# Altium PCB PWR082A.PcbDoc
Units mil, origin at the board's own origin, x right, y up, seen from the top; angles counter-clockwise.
Board outline 3000 x 2000 mil, 4 copper layers (Top, Inner Layer 2, Inner Layer 3, Bottom), stack 35.4 mil thick; 57 components, 21 nets, 108 pads, 176 vias.
Unrouted connection lines stored in the file: 167.
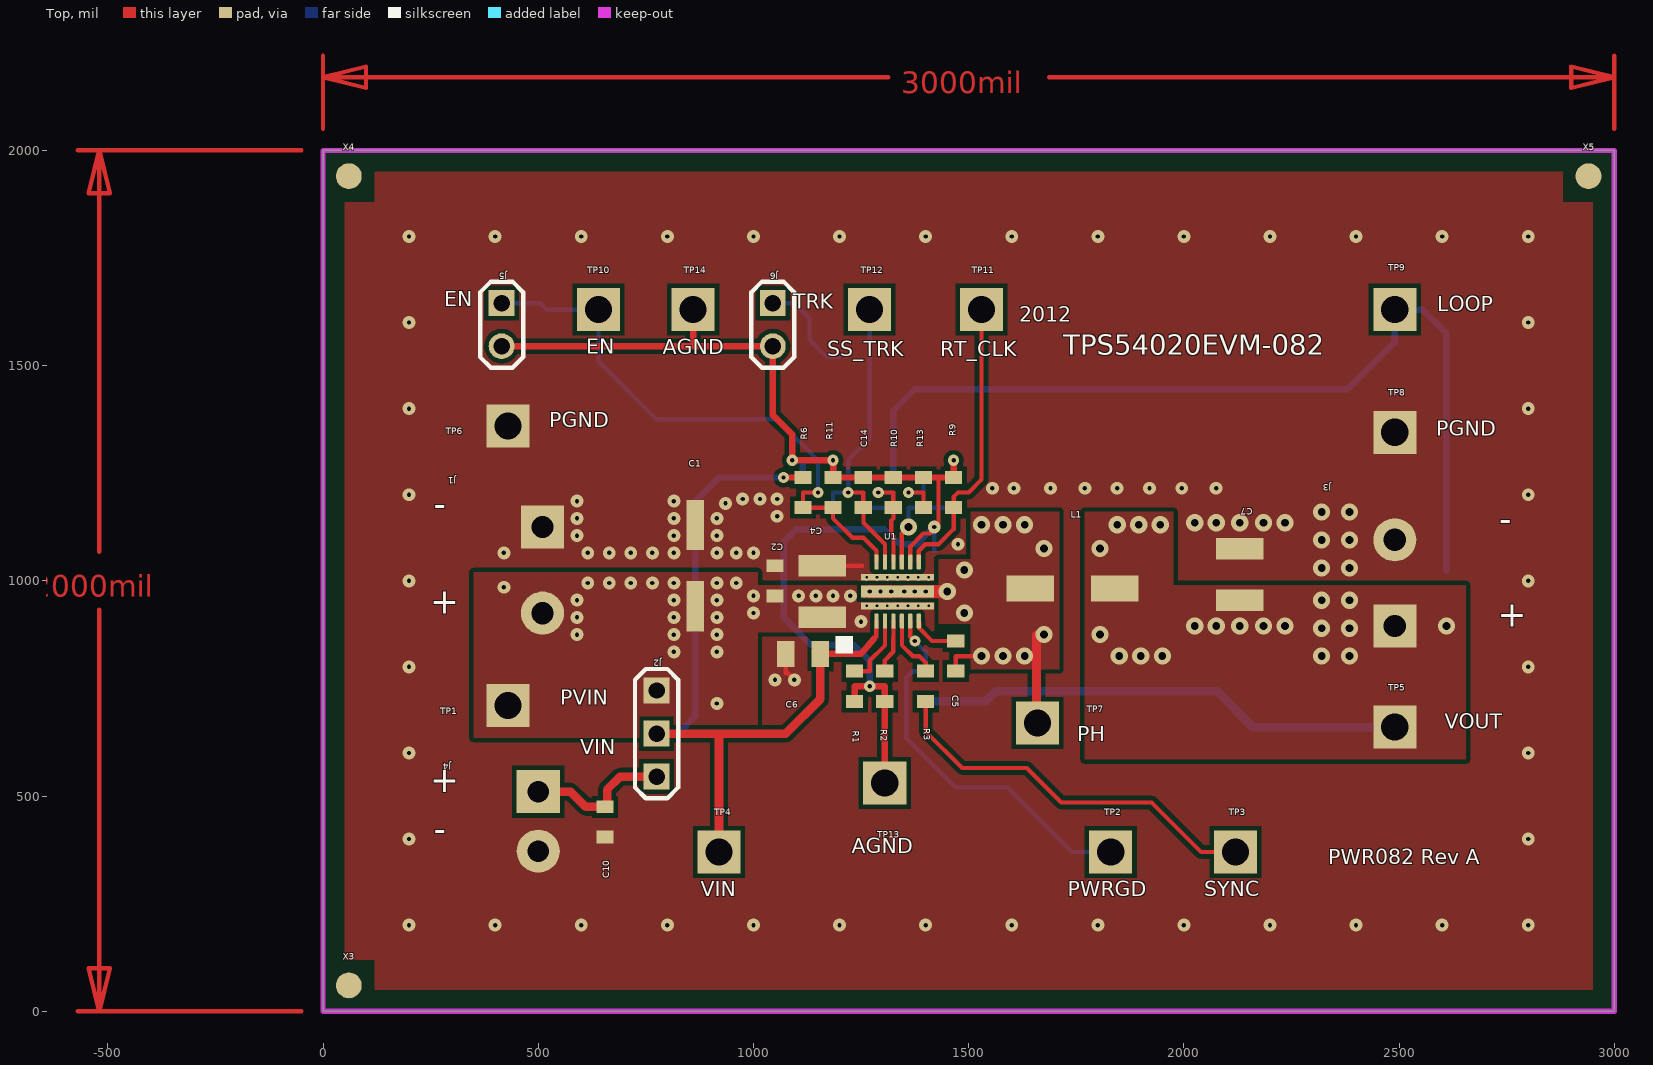
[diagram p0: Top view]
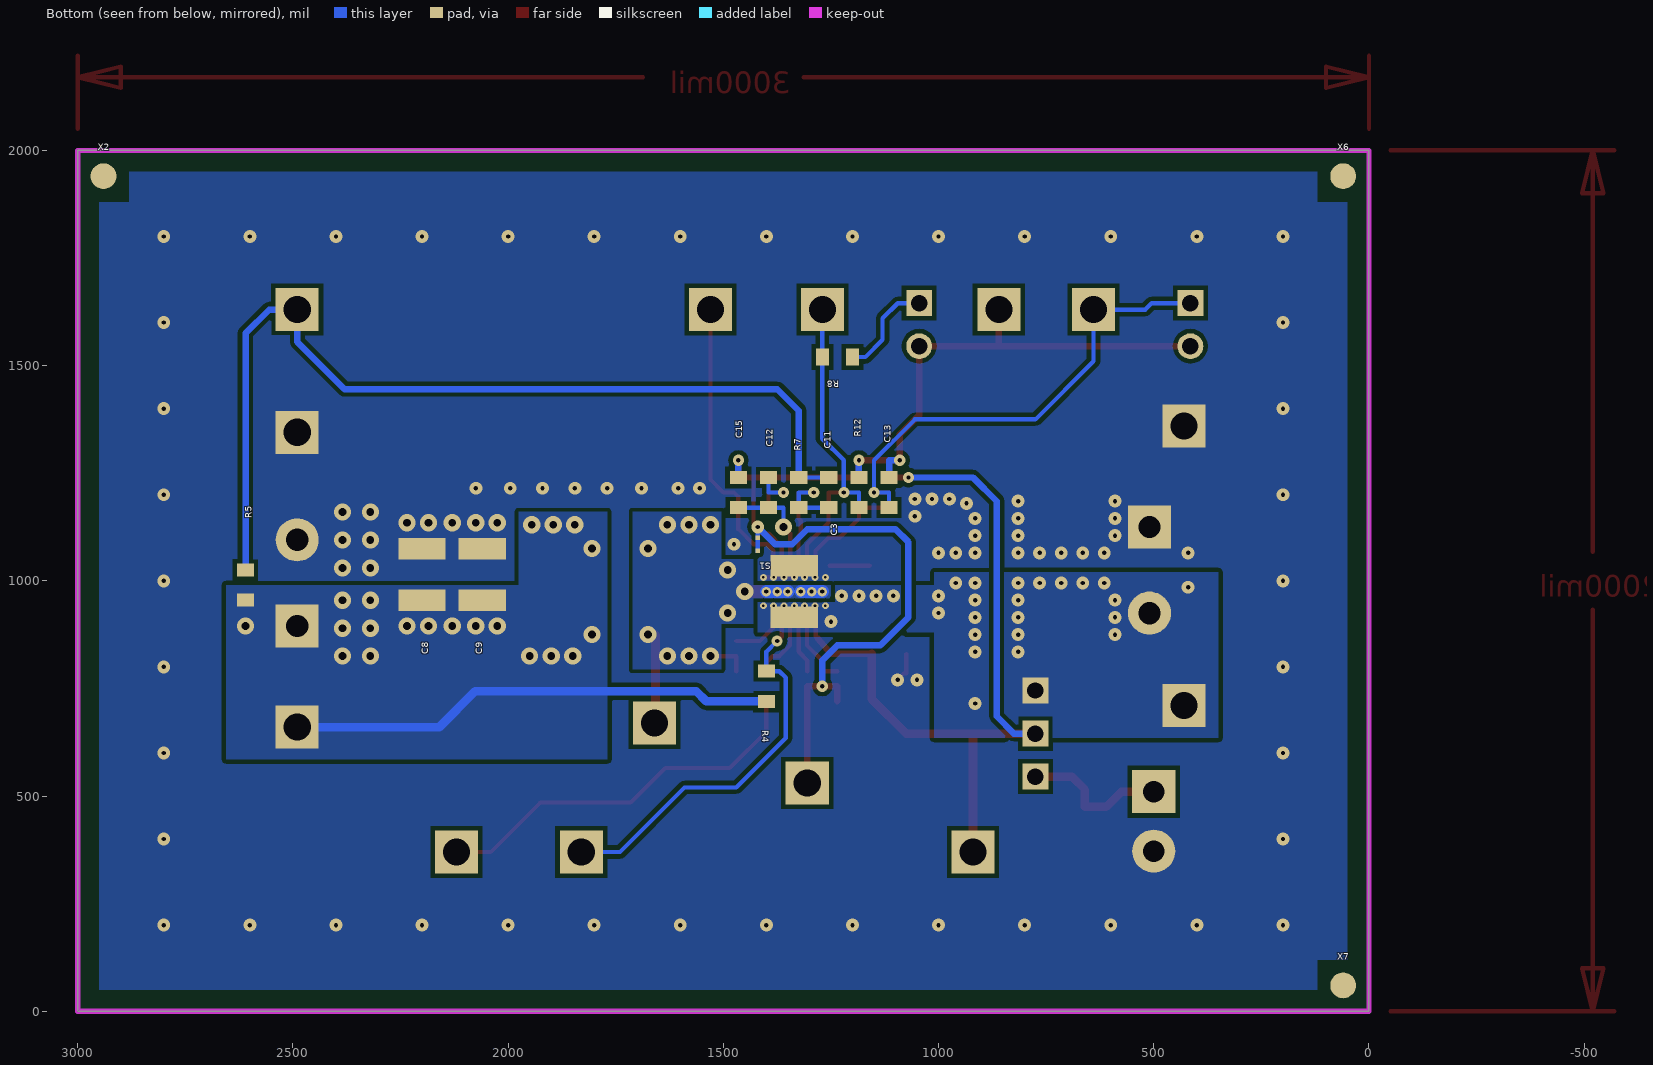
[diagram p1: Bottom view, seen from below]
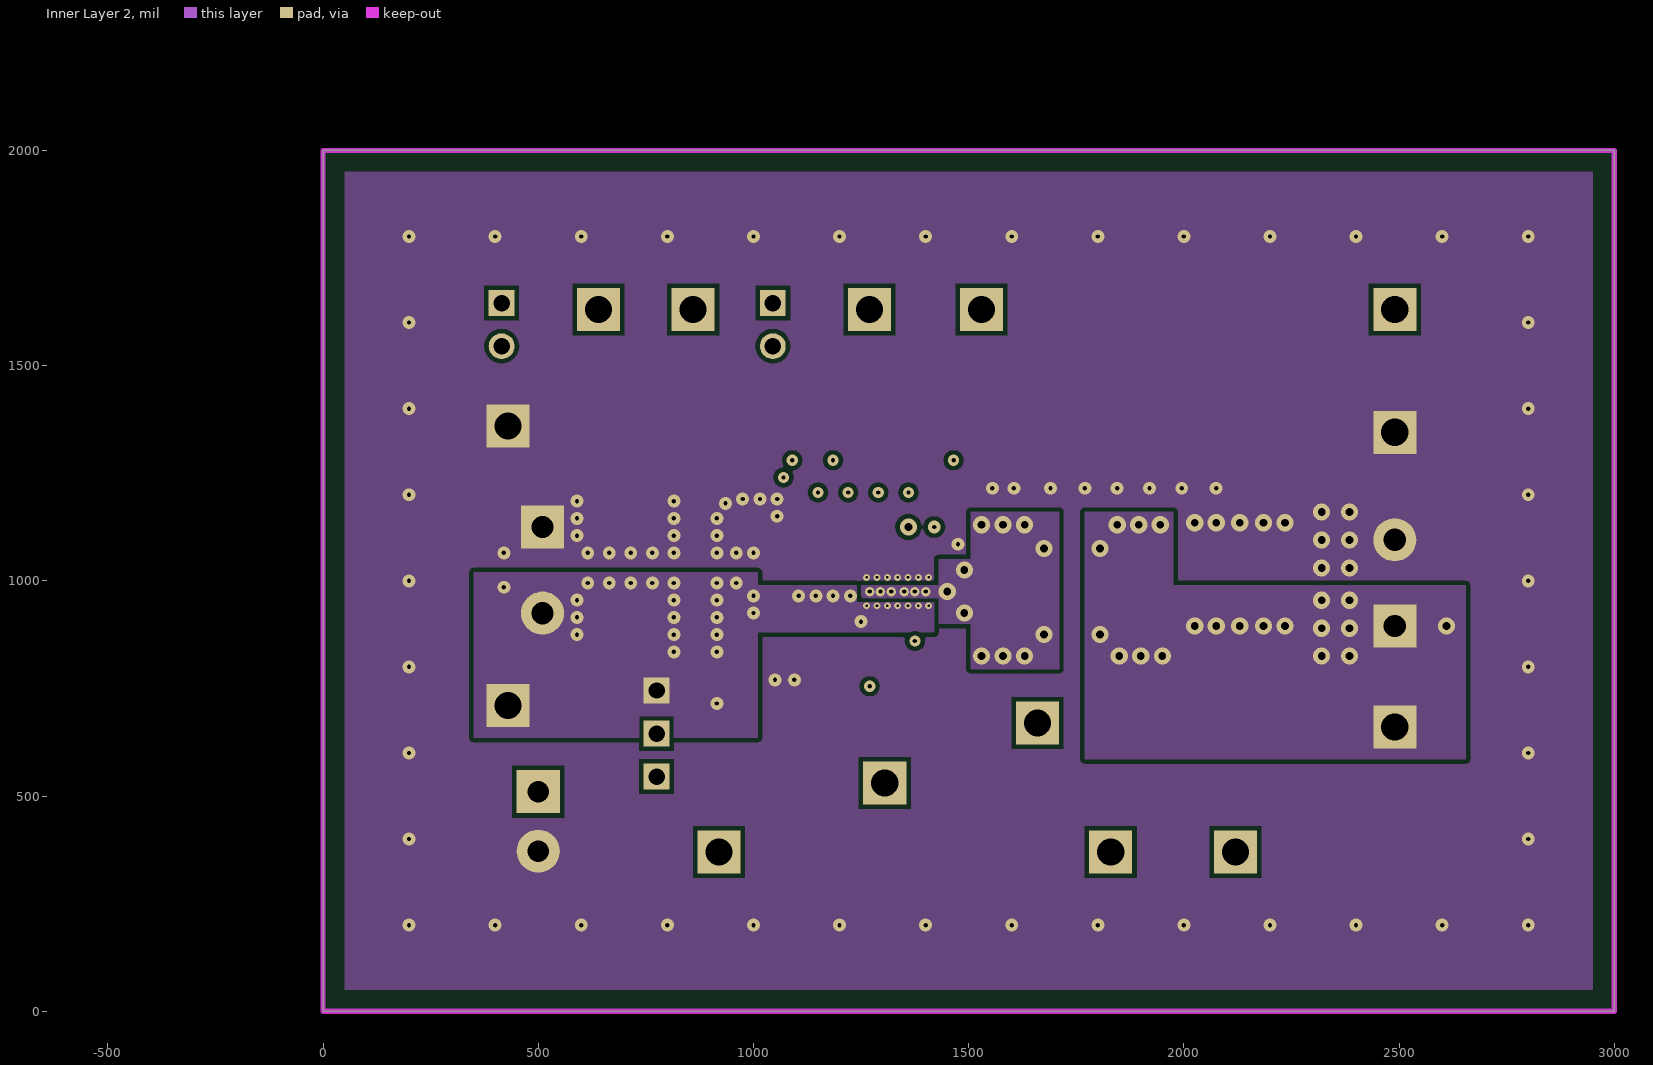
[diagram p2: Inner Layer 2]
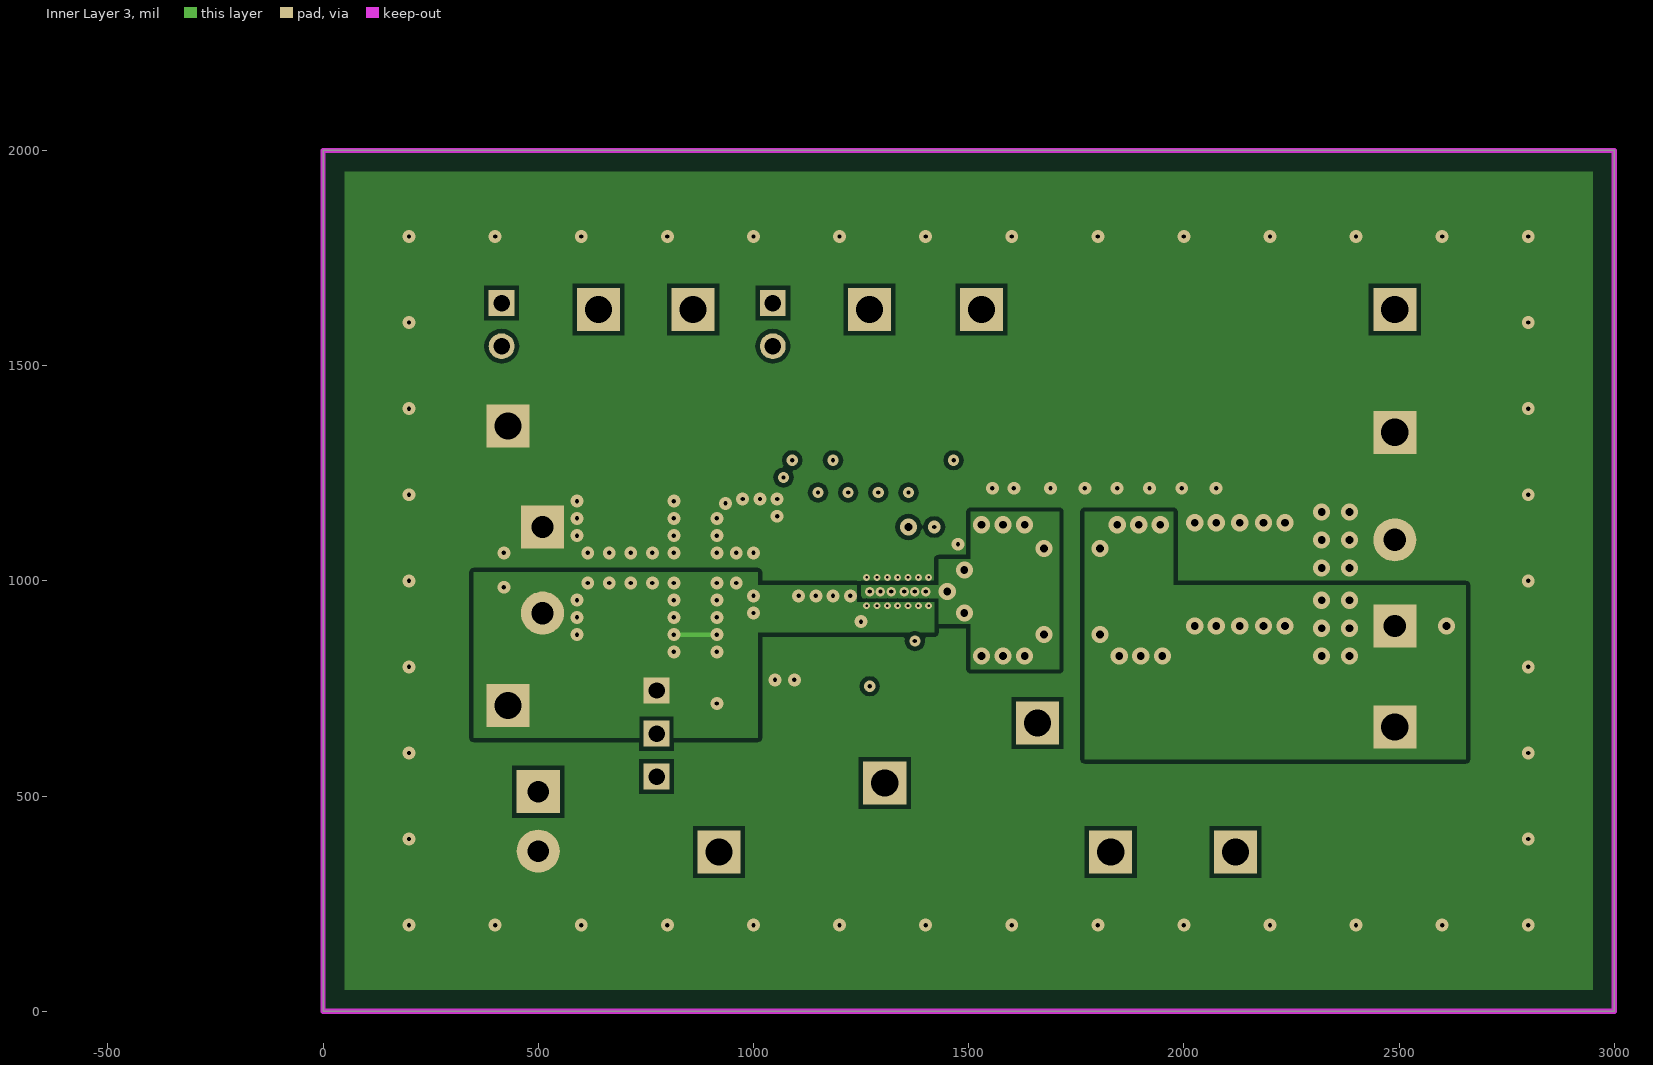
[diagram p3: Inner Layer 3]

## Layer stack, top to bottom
Solder Mask Top: solder mask 0.4, Solder Resist, Dk 3.5
Top: signal copper 1.35
Dielectric 1: dielectric 10, FR-4, Dk 4.3
Inner Layer 2: signal copper 1.35
Dielectric2: dielectric 10, FR-4, Dk 4.3
Inner Layer 3: signal copper 1.35
Dielectric3: dielectric 10, FR-4, Dk 4.3
Bottom: signal copper 1.35
Solder Mask Bottom: solder mask 0.4, Solder Resist, Dk 3.5

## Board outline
0,0 3000,0 3000,2000 0,2000

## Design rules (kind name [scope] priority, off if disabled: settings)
Clearance "Clearance - Default - DEFAULT- SMD" [IsVia vs IsSMTPin] p1: gap=10 ignorepadtopadclearanceinfootprint=FALSE
Clearance "Clearance - Default - DEFAULT - Via" [IsVia vs IsVia] p2: gap=10 ignorepadtopadclearanceinfootprint=FALSE
Clearance "Clearance - Default - DEFAULT - Net" [All] p3: gap=10 ignorepadtopadclearanceinfootprint=FALSE except(0: Arc-Hole Track-Hole SMDPad-Hole THPad-Hole Via-Hole Fill-Hole Poly-Hole Region-Hole Text-Hole; 1: Arc-Text Track-Text SMDPad-Text THPad-Text Via-Text Fill-Text Poly-Text Region-Text; 8: Arc-Arc Arc-Track Arc-SMDPad Arc-THPad Track-Track Track-SMDPad Track-THPad SMDPad-SMDPad SMDPad-THPad SMDPad-Via THPad-THPad)
ComponentClearance "ComponentClearance - Default - DEFAULT" [All] p1: gap=6 collisioncheckmode=3 verticalgap=10 showdistances=FALSE
HoleToHoleClearance "HoleToHoleClearance - Default - DEFAULT" [All] p1: gap=6 allowstackedmicrovias=TRUE
Length "Default Length" [All] p1: maxlimit=50000 minlimit=0
MaxMinImpedance "Default Impedance" [All] p1: minimum=50.00 maximum=150.0
ParallelSegment "Default Parallel Segment Same Layer" [All] p1: limit=1000 gap=200
ParallelSegment "Default Parallel Segment Adjasent" [All] p2: limit=1000 gap=200
PlaneConnect "Default PlaneConnect" [All] p1: planeconnectstyle=Direct reliefexpansion=20 reliefentries=4 reliefconductorwidth=10 reliefairgap=10
PolygonConnect "PolygonConnect - Default SMT" [IsSMTPin] p1: connectstyle=Direct reliefconductorwidth=10 reliefentries=4 polygonreliefangle="45 Angle" airgapwidth=10
PolygonConnect "PolygonConnect - Default Pad" [All] p2: connectstyle=Direct reliefconductorwidth=10 reliefentries=4 polygonreliefangle="45 Angle" airgapwidth=10
RoutingLayers "RoutingLayers - Default - DEFAULT" [All] p1: top layer_v5=TRUE mid layer 1_v5=TRUE mid layer 2_v5=TRUE bottom layer_v5=TRUE
RoutingPriority "RoutingPriority - Default - DEFAULT" [All] p1: routingpriority=3
RoutingTopology "Default Routing Topology" [All] p1: topology=Shortest
RoutingVias "RoutingVias - Default - DEFAULT" [All] p1: holewidth=37 width=55 viastyle="Through Hole" minholewidth=37 minwidth=55 maxholewidth=37 maxwidth=55
SMDToCorner "SMDToCorner - Default - DEFAULT" [All] p1: distance=100000
SolderMaskExpansion "SolderMaskExpansion from CAM settings" [All] p1: expansion=1
Width "Default Width" [All] p1: maxlimit=25 minlimit=6 preferedwidth=10
22 further rules are at their usual default settings.

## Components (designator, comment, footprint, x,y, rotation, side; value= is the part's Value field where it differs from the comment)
C1 "CAP_ALUM_FK-D" CAP_ALUM_FK-D 865,1035 r180 top
C2 "C603" C603 1050,1000 r270 top
C3 "C1210" C1210 1335,975 r90 bottom
C4 "C1210" C1210 1160,975 r90 top
C5 "C603" C603 1470,825 r90 top
C6 "C0805" C0805 1115,830 r0 top
C7 "C1210" C1210 2130,1015 r90 top
C8 "C1210" C1210 2200,1015 r90 bottom
C9 "C1210" C1210 2060,1015 r90 bottom
C10 "C603" C603 655,440 r90 top
C11 "C603" C603 1255,1205 r90 bottom
C12 "C603" C603 1395,1205 r270 bottom
C13 "C603" C603 1115,1205 r270 bottom
C14 "C603" C603 1255,1205 r270 top
C15 "C603" C603 1465,1205 r270 bottom
J1 "TB_2X5.1MM" TB_2X5.1MM 510,1125 r270 top
J2 "HDR100_1X3" HDR100_1X3 775,745 r270 top
J3 "TB_2X5.1MM" TB_2X5.1MM 2490,895 r90 top
J4 "TB_2X3.5MM" TB_2X3.5MM 500,510 r270 top
J5 "HDR100_1X2" HDR100_1X2 415,1645 r270 top
J6 "HDR100_1X2" HDR100_1X2 1045,1645 r270 top
L1 "IND_272_X_276" IND_272_X_276 1741,982 r0 top
R1 "R603" R603 1235,755 r270 top
R2 "R603" R603 1305,755 r270 top
R3 "R603" R603 1400,755 r90 top
R4 "R603" R603 1400,755 r90 bottom
R5 "R603" R603 2610,990 r90 bottom
R6 "R603" R603 1115,1205 r270 top
R7 "R603" R603 1325,1205 r270 bottom
R8 "R603" R603 1235,1520 r0 bottom
R9 "R603" R603 1465,1205 r90 top
R10 "R603" R603 1325,1205 r90 top
R11 "R603" R603 1185,1205 r90 top
R12 "R603" R603 1185,1205 r90 bottom
R13 "R603" R603 1395,1205 r90 top
S1 "WIRE" WIRE 1420,1070 r0 bottom
TP1 "TH-63" TH-63 430,710 r0 top
TP2 "TH-63" TH-63 1830,370 r0 top
TP3 "TH-63" TH-63 2120,370 r0 top
TP4 "TH-63" TH-63 920,370 r0 top
TP5 "TH-63" TH-63 2490,660 r0 top
TP6 "TH-63" TH-63 430,1360 r0 top
TP7 "TH-63" TH-63 1660,670 r0 top
TP8 "TH-63" TH-63 2490,1345 r0 top
TP9 "TH-63" TH-63 2490,1630 r0 top
TP10 "TH-63" TH-63 640,1630 r0 top
TP11 "TH-63" TH-63 1530,1630 r0 top
TP12 "TH-63" TH-63 1270,1630 r0 top
TP13 "TH-63" TH-63 1305,530 r0 top
TP14 "TH-63" TH-63 860,1630 r0 top
U1 "QFN15[RUW]" QFN15[RUW] 1335,975 r0 top
X2 "TOP_FIDO_60-MIL" TOP_FIDO_60-MIL 2940,1940 r180 bottom
X3 "TOP_FIDO_60-MIL" TOP_FIDO_60-MIL 60,60 r0 top
X4 "TOP_FIDO_60-MIL" TOP_FIDO_60-MIL 60,1940 r0 top
X5 "TOP_FIDO_60-MIL" TOP_FIDO_60-MIL 2940,1940 r0 top
X6 "TOP_FIDO_60-MIL" TOP_FIDO_60-MIL 60,1940 r180 bottom
X7 "TOP_FIDO_60-MIL" TOP_FIDO_60-MIL 60,60 r180 bottom

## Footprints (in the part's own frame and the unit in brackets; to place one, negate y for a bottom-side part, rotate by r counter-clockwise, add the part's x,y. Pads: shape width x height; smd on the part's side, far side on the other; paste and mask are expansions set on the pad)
C603 [mil]
  rect 30x40 smd mask+2: 1(-35,0) 2(35,0)
C0805 [mil]
  rect 40x60 smd mask+2: 1(-40,0) 2(40,0)
C1210 [mil]
  rect 50x110 smd mask+2: 1(60,0) 2(-60,0)
CAP_ALUM_FK-D [mil]
  rect 40x117 smd: 1(0,94.5) 2(0,-94.5)
HDR100_1X2 [mil]
  rect 60x60 hole 38: 1(0,0)
  round 60 hole 38: 2(100,0)
  silkscreen extent -50,-50 150,50
HDR100_1X3 [mil]
  rect 60x60 hole 38: 1(0,0) 2(100,0) 3(200,0)
  silkscreen extent -50,-50 250,50
IND_272_X_276 [mil]
  rect 110x60 smd: 1(-98,0) 2(98,0)
QFN15[RUW] [mil]
  rrect50% 10x35 smd mask+2: 1(-49.25,-68.47) 2(-29.55,-68.47) 3(-9.85,-68.47) 4(9.85,-68.47) 5(29.55,-68.47) 6(49.25,-68.47) 10(49.25,68.47) 11(29.55,68.47) 12(9.85,68.47) 13(-9.85,68.47) 14(-29.55,68.47) 15(-49.25,68.47)
  rect 169.29x15.75 smd mask+0.98: 7(0,-33.46) 9(0,33.46)
  rect 169.29x27.56 smd mask+0.98: 8(0,0)
  silkscreen extent -144,-144 -104,-104
R603 [mil]
  rect 30x40 smd: 1(-35,0) 2(35,0)
TB_2X3.5MM [mil]
  rect 100x100 hole 50: 1(0,0)
  round 100 hole 50: 2(138,0)
TB_2X5.1MM [mil]
  rect 100x100 hole 52: 1(0,0)
  round 100 hole 52: 2(200,0)
TH-63 [mil]
  rect 100x100 hole 63: 1(0,0)
TOP_FIDO_60-MIL [mil]
  round 60 smd: 1(0,0)
  Top pour cut-out: -60,60 60,60 60,-60 -60,-60 -60,60
WIRE [mil]
  rect 10x10 smd: 1(0,0) 2(0,-30)

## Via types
v1: diameter 30, hole 10, Top to Bottom, 103 vias
v2: diameter 40, hole 18, Top to Bottom, 43 vias
v3: diameter 16, hole 6, Top to Bottom, 14 vias
v4: diameter 26, hole 10, Top to Bottom, 10 vias
v5: diameter 22, hole 10, Top to Bottom, 6 vias

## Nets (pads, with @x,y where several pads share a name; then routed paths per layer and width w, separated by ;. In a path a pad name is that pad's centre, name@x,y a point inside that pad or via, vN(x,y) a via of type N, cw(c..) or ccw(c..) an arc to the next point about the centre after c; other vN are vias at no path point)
$$$3415: C12.1 R13.1 | length 140
  Top w10: v4(1360,1205) 1395,1205 R13.1
  Bottom w10: v4(1360,1205) 1395,1205 C12.1
$$$5685: J6.1 R8.1 | length 236.1
  Bottom w10: J6.1 1095,1645 1130,1610 1130,1560 1170,1520 R8.1
AGND: C13.1 C14.1 C15.1 J5.2 J6.2 R1.2 R2.2 R9.2 R10.2 R11.2 R12.2 R13.2 S1.2 TP13.1 TP14.1 U1.11 | length 3057.2
  Top w10: U1.11 1364.55,1080 1394.55,1110 1410,1110 v1(1420,1125) 1430,1130 1430,1240
  Top w15: J5.2 860,1545 ; TP14.1 860,1545 ; R1.2 1235,755 v4(1270,755) 1305,755 R2.2 TP13.1 ; v4(1465,1280) R9.2 1430,1240 R13.2 R10.2 C14.1 R11.2 v4(1185,1280) v4(1090,1280) 1090,1340 1045,1385 J6.2 860,1545
  Bottom w10: S1.2 v1(1420,1125)
  Bottom w15: v4(1090,1280) 1115,1280 C13.1 ; R12.2 v4(1185,1280) ; v4(1270,755) 1270,815 1235,850 1135,850 1070,915 1070,1090 1100,1120 1305,1120 1340,1085 1380,1085 v1(1420,1125) ; C15.1 v4(1465,1280)
BOOT: C5.2 U1.6 | length 114
  Top w10: U1.6 1385,902.58 1385,890 1415,860 C5.2
COMP: C12.2 C15.2 U1.12 | length 237.9
  Top w10: U1.12 1344.85,1110 v2(1360,1125)
  Bottom w10: v2(1360,1125) 1360,1170 C12.2 C15.2
EN: C13.2 J5.1 R6.2 R11.1 TP10.1 U1.15 | length 1424.8
  Top w10: v4(1150,1205) 1115,1205 R6.2 R11.1 1185,1145 1230,1100 1255.75,1100 1285.75,1070 U1.15
  Bottom w10: J5.1 505,1645 520,1630 TP10.1 640,1540 640,1510 775,1375 1055,1375 1150,1280 v4(1150,1205) 1115,1205 C13.2
HICCUP: R1.1 U1.2 | length 166.3
  Top w10: R1.1 1270,790 1270,815 1305.45,850 U1.2
ILIM: R2.1 U1.3 | length 124.8
  Top w10: R2.1 1305,815 1325,835 U1.3
LOOP: C11.2 R5.2 R7.1 TP9.1 | length 2224.1
  Bottom w10: C11.2 R7.1
  Bottom w15: R7.1 1325,1395 1375,1445 2380,1445 2490,1555 TP9.1 2555,1630 2610,1575 R5.2
PGND: C1.2 C2.1 C3.1 C4.1 C6.1 C7.1 C8.1 C9.1 C10.1 J1.1 J3.2 J4.2 S1.1 TP6.1 TP8.1 U1.9 | length 239.3
  Top w10: C6.1 1075,785 1080,785 v1(1095,770) ; C4.1 1253,1035 ; U1.9 1336.54,1008 U1.9@1410,1008
  other v1: 200,200 400,200 600,200 800,200 1000,200 1200,200 1400,200 1600,200 1800,200 2000,200 2200,200 2400,200 2600,200 2800,200 200,400 2800,400 200,600 2800,600 1050,770 200,800 2800,800 200,1000 2800,1000 420,1065 615,1065 665,1065 715,1065 765,1065 815,1065 915,1065 960,1065 1000,1065 1475,1085 590,1105 815,1105 915,1105 590,1145 815,1145 915,1145 1055,1150 935,1180 590,1185 815,1185 975,1190 1015,1190 1055,1190 200,1200 2800,1200 1555,1215 1605,1215 1690,1215 1770,1215 1845,1215 1920,1215 1995,1215 2075,1215 200,1400 2800,1400 200,1600 2800,1600 200,1800 400,1800 600,1800 800,1800 1000,1800 1200,1800 1400,1800 1600,1800 1800,1800 2000,1800 2200,1800 2400,1800 2600,1800 2800,1800
  other v2: 2320,1030 2385,1030 2320,1095 2385,1095 2025,1135 2075,1135 2130,1135 2185,1135 2235,1135 2320,1160 2385,1160
  other v3: 1263,1008 1287,1008 1311,1008 1335,1008 1359,1008 1383,1008 1407,1008
PH: C5.1 L1.1 TP7.1 U1.8 | length 598.5
  Top w6: v5(1320,975) v5(1350,975)
  Top w10: C5.1 1470,825 v2(1530,825)
  Top w20: TP7.1 1657.52,672.48 1657.52,805 1657.52,875 v2(1675,875)
  Top w30: v5(1270,975) v5(1295,975) v5(1320,975) ; v5(1350,975) v5(1375,975) v5(1400,975) v2(1450,975)
  Bottom w30: v5(1270,975) v5(1295,975) v5(1320,975) ; v5(1350,975) v5(1375,975) v5(1400,975)
  other v2: 1580,825 1630,825 1490,925 1490,1025 1675,1075 1530,1130 1580,1130 1630,1130
PVIN: C1.1 C2.2 C3.2 C4.2 J1.2 J2.1 TP1.1 U1.7 | length 100
  Inner Layer 3 w10: v1(815,875) v1(915,875)
  other v1: 915,715 815,835 915,835 590,875 1250,905 590,915 815,915 915,915 1000,925 590,955 815,955 915,955 1000,965 1105,965 1145,965 1185,965 1225,965 420,985 615,995 665,995 715,995 765,995 815,995 915,995 960,995
  other v3: 1263,942 1287,942 1311,942 1335,942 1359,942 1383,942 1407,942
PWRGD: R4.2 TP2.1 U1.5 | length 907.5
  Top w10: U1.5 1364.55,870 1365,870 v4(1375,860)
  Bottom w10: v4(1375,860) 1400,835 R4.2 1370,790 1355,775 1355,635 1470,520 1590,520 1740,370 TP2.1
RT_CLK: R9.1 TP11.1 U1.10 | length 679.6
  Top w10: U1.10 1384.25,1070 1399.25,1085 1430,1085 1465,1120 R9.1 1465,1195 1475,1205 1500,1205 1530,1235 TP11.1
SS_TR: C14.2 R8.2 R12.1 TP12.1 U1.14 | length 733.1
  Top w10: v4(1220,1205) 1255,1205 C14.2 1255.45,1169.55 1255.45,1135 1305.45,1085 U1.14
  Bottom w10: R12.1 1185,1205 v4(1220,1205) 1220,1280 1270,1330 1270,1450 R8.2 TP12.1
SYNC_OUT: R3.2 U1.4 | length 148.2
  Top w10: U1.4 1345,906.38 1345,850 1370,825 1385,825 1400,810 R3.2
SYNC_TP: R3.1 TP3.1 | length 906
  Top w10: R3.1 1400,650 1485,565 1635,565 1715,485 1925,485 2040,370 TP3.1
VIN: C6.2 J2.2 R6.1 TP4.1 U1.1 | length 1857.2
  Top w10: 1280,865 1285,870 U1.1
  Top w15: v4(1070,1240) R6.1 ; C6.2 1250,830 1280,865
  Top w20: J2.2 920,645 ; TP4.1 920,645 ; C6.2 1155,725 1075,645 920,645
  Bottom w15: J2.2 825,645 865,685 865,1185 920,1240 v4(1070,1240)
VIN_SRC: C10.2 J2.3 J4.1 | length 341.9
  Top w20: J4.1 575,510 610,475 660,475 660,515 690,545 J2.3
VOUT: C7.2 C8.2 C9.2 J3.1 L1.2 R4.1 R5.1 TP5.1 | length 1134.5
  Bottom w20: R4.1 1539.75,720 1563.44,743.69 2076.23,743.77 2160,660 TP5.1
  other v2: 1850,825 1900,825 1950,825 2320,825 2385,825 1805,875 2320,890 2385,890 2025,895 2075,895 2130,895 2185,895 2235,895 2610,895 2320,955 2385,955 1805,1075 1845,1130 1895,1130 1945,1130
VSENSE: C11.1 R7.2 R10.1 U1.13 | length 340.7
  Top w10: v4(1290,1205) 1325,1205 R10.1 1325.15,1169.85 1325.15,1144.85 1320.15,1139.85 1320.15,1110 1325.15,1105 U1.13
  Bottom w10: C11.1 R7.2 1325,1205 v4(1290,1205)
pads on no net: X2.1 X3.1 X4.1 X5.1 X6.1 X7.1
copper on no net: | length 6896.1
  Top w10: -570,0 -50,0 ; -570,2000 -50,2000 ; -520,932.5 -520,0 ; -520,1067.5 -520,2000 ; 0,2050 0,2220 ; 1313.18,2170 0,2170 ; 1686.82,2170 3000,2170 ; 3000,2050 3000,2220 ; -520,0 -495,100 -545,100 -520,0 ; -520,2000 -545,1900 -495,1900 -520,2000 ; 0,2170 100,2145 100,2195 0,2170 ; 3000,2170 2900,2195 2900,2145 3000,2170

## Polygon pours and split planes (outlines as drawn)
PVIN on Inner Layer 3 "Inner Layer 3-PVIN" (solid, remove dead copper, pour order 20): 350,1020 350,635 1010,635 1010,880 1420,880 1420,950 1240,950 1240,990 1010,990 1010,1020
PH on Inner Layer 3 "Inner Layer 3-PH" (solid, remove dead copper, pour order 16): 1250,990 1250,960 1430,960 1430,900 1505,900 1505,795 1710,795 1710,1160 1505,1160 1505,1050 1430,1050 1430,990
VOUT on Inner Layer 3 "Inner Layer 3-VOUT" (solid, remove dead copper, pour order 18): 1770,1160 1770,585 2655,585 2655,990 1975,990 1975,1160
PGND on Inner Layer 3 "Inner Layer 3-PGND" (solid, remove dead copper, pour order 22): 2950,50 2950,1950 50,1950 50,50
PGND on Inner Layer 2 "Inner Layer 2-PGND" (solid, remove dead copper, pour order 14): 2950,1950 50,1950 50,50 2950,50
PVIN on Inner Layer 2 "Inner Layer 2-PVIN" (solid, remove dead copper, pour order 12): 350,1020 350,635 1010,635 1010,880 1420,880 1420,950 1240,950 1240,990 1010,990 1010,1020
PH on Inner Layer 2 "Inner Layer 2-PH" (solid, remove dead copper, pour order 8): 1250,990 1250,960 1430,960 1430,900 1505,900 1505,795 1710,795 1710,1160 1505,1160 1505,1050 1430,1050 1430,990
VOUT on Inner Layer 2 "Inner Layer 2-VOUT" (solid, remove dead copper, pour order 10): 1770,1160 1975,1160 1975,990 2655,990 2655,585 1770,585
PH on Top "Top-PH" (solid, remove dead copper, pour order 0): 1250,960 1430,960 1430,900 1505,900 1505,795 1710,795 1710,1160 1505,1160 1505,1050 1430,1050 1430,990 1250,990
VOUT on Top "Top-VOUT" (solid, remove dead copper, pour order 2): 1770,1160 1975,1160 1975,990 2655,990 2655,585 1770,585
PGND on Top "Top-PGND" (solid, remove dead copper, pour order 6): 50,1950 50,50 2950,50 2950,1950
PVIN on Top "Top-PVIN" (solid, remove dead copper, pour order 4): 350,1020 350,635 1010,635 1010,880 1420,880 1420,950 1240,950 1240,990 1010,990 1010,1020
PH on Bottom "Bottom-PH" (solid, remove dead copper, pour order 24): 1250,990 1250,960 1430,960 1430,900 1505,900 1505,795 1710,795 1710,1160 1505,1160 1505,1050 1430,1050 1430,990
VOUT on Bottom "Bottom-VOUT" (solid, remove dead copper, pour order 26): 1975,1160 1770,1160 1770,585 2655,585 2655,990 1975,990
PVIN on Bottom "Bottom-PVIN" (solid, remove dead copper, pour order 28): 1420,880 1010,880 1010,635 350,635 350,1020 1010,1020 1010,990 1240,990 1240,950 1420,950
PGND on Bottom "Bottom-PGND" (solid, remove dead copper, pour order 30): 50,50 2950,50 2950,1950 50,1950

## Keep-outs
Keep-Out Layer:
  the board outline again, w12

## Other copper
Top:
  text "3000mil" at 1343.18,2132.5 h50
  text "2000mil" at -676.82,962.5 h50
  text "L1" at 2020.29,-1012.24 h62.5
Inner Layer 2:
  text "L2" at 2256.9,-1012.24 h62.5
Inner Layer 3:
  text "L3" at 2506.9,-1012.24 h62.5
Bottom:
  region: 1415,1105 1425,1105 1425,1065 1415,1065 1415,1105
  text "L4" at 2755.41,-1012.24 h62.5

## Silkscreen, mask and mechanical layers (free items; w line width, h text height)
Silkscreen Top:
  text "EN" at 282.03,1625.8 h60
  text "TRK" at 1092.03,1620.8 h60
  text "LOOP" at 2588.57,1615.13 h60
  text "2012" at 1617.47,1590.38 h60
  text "EN" at 612.03,1515.8 h60
  text "AGND" at 788.88,1515.13 h60
  text "SS_TRK" at 1171.88,1510.14 h60
  text "RT_CLK" at 1434.27,1510.14 h60
  text "TPS54020EVM-082" at 1720,1508.51 h80
  text "PGND" at 525.99,1345.13 h60
  text "PGND" at 2585.99,1325.13 h60
  text "-" at 257.84,1131.07 h100
  text "-" at 2732.84,1096.07 h100
  text "+" at 248.91,903.86 h100
  text "+" at 2728.91,873.86 h100
  text "PVIN" at 551.64,700.8 h60
  text "VOUT" at 2606.1,645.13 h60
  text "PH" at 1751.98,615.8 h60
  text "VIN" at 597.54,585.8 h60
  text "+" at 248.91,488.86 h100
  text "-" at 257.84,376.07 h100
  text "AGND" at 1228.88,355.13 h60
  text "PWR082 Rev A" at 2335,330.38 h60
  text "VIN" at 877.54,255.8 h60
  text "PWRGD" at 1730.65,255.13 h60
  text "SYNC" at 2047.74,255.13 h60
  text "S1" at 3013.74,-1012.24 h62.5
Silkscreen Bottom:
  text "S4" at 3248.61,-1012.49 h62.5
Paste Mask Top:
  text "P1" at 4013.49,-1017.49 h62.5
Paste Mask Bottom:
  text "P4" at 4248.86,-1017.24 h62.5
Solder Mask Top:
  text "M1" at 3508.58,-1012.49 h62.5
Solder Mask Bottom:
  text "M4" at 3743.95,-1012.24 h62.5
Assembly Drawing Top:
  text "TA" at 4500.4,-1012.49 h62.5
Assembly Drawing Bottom:
  text "BA" at 4747.37,-1012.24 h62.5
Layer_15:
  lines w5: 1930,-850 2180,-850 ; 2430,-1100 2455,-1100
  lines w10: 610,-1250 610,-1100 ; 1510,-1250 1510,-1100 ; 1930,-850 3930,-850 ; 1930,-700 3930,-700 ; 2180,-1100 2180,-700 ; 2300,-1250 2300,-1100 ; 2430,-1100 2430,-850 ; 2680,-850 2680,-1100 2680,-700 ; 2930,-850 5430,-850 ; 2930,-700 4930,-700 ; 3050,-1250 3050,-1100 ; 3180,-1100 3180,-700 ; 3430,-1100 3430,-700 ; 3680,-1100 3680,-700 ; 4180,-1105 4180,-705 ; 4680,-1250 4680,-1100 4680,-700
  lines w20: 5,-1100 5430,-1100 ; 5,-850 1930,-850 ; 1305,-1100 1305,-850 ; 1930,-1095 1930,-550 ; 2930,-1095 2930,-550 ; 3430,-1095 3430,-550 ; 3930,-1100 3930,-555 ; 4430,-1095 4430,-550 ; 4930,-1095 4930,-550 ; 5,-1250 5430,-1250 5430,-550 5,-550 5,-1250
  text "S Mask" at 3565.39,-652.75 h45.5
  text "Silkscreen" at 3033.22,-653.83 h45.5
  text "P Mask" at 4065.39,-657.75 h45.5
  text "Copper Layer Name" at 2117.72,-660.33 h45.5
  text "Assembly" at 4533.44,-660.33 h45.5
  text "Drill Drawing" at 5022.99,-722.61 h40
  text "TEXAS INSTRUMENTS" at 180,-744.99 h75
  text "Internal" at 2315.02,-804.99 h50
  text "Bot" at 2747.27,-804.99 h50
  text "Bot" at 3247.27,-804.99 h50
  text "Bot" at 3747.27,-804.99 h50
  text "Bot" at 4747.27,-804.99 h50
  text "Bot" at 4247.27,-809.99 h50
  text "Top" at 1995.13,-813.33 h50
  text "Top" at 2995.13,-813.33 h50
  text "Top" at 3495.13,-813.33 h50
  text "Top" at 4495.13,-813.33 h50
  text "Top" at 3995.13,-818.33 h50
  text "Board No." at 55,-915 h25
  text "Rev." at 1330,-915 h25
  text "PWR082" at 370,-1025 h50
  text "A" at 1420,-1025 h50
  text "Date:" at 30,-1165 h25
  text "Software" at 4710,-1165 h25
  text "Filename:" at 630,-1165.59 h25
  text "Modified Date:" at 3085,-1165.59 h25
  text "PCB Dsgnr:" at 2335,-1169.16 h25
  text "Engineer:" at 1545,-1169.76 h25
  text "8/01/2012" at 170,-1200 h30
  text "PWR082A.PCB" at 870,-1200 h30
  text "M. Cardella" at 1770,-1200 h30
  text "M. Cardella" at 2620,-1200 h30
  text "8/07/2012" at 3420,-1200 h30
  text "PADs  9.3" at 4920,-1200 h30
Drill Drawing:
  drawing of 148 lines, arcs and shapes, not listed
  text "FABRICATION CHART" at 8969.2,6970.01 h100
  text "FINISHED COPPER WEIGHT" at 10893,6655.01 h75
  text "FINISHED" at 6885.76,6645.01 h75
  text "SILKSCREEN" at 7999.35,6545.01 h75
  text "SOLDERMASK" at 9260.07,6545.01 h75
  text "THICKNESS" at 6820.95,6445.01 h75
  text "EXTERNAL" at 10613.27,6395.01 h75
  text "INTERNAL" at 11982.91,6395.01 h75
  text "0.031" at 6895,6202.51 h62.5
  text "LAYER 1" at 8095,6202.51 h62.5
  text "LAYER 1" at 9395,6202.51 h62.5
  text "1 OZ." at 10645,6202.51 h62.5
  text "1 OZ." at 11910,6202.51 h62.5
  text "0.062" at 6895,6002.51 h62.5
  text "LAYER 2" at 8095,6002.51 h62.5
  text "LAYER 2" at 9395,6002.51 h62.5
  text "2 OZ." at 10645,6002.51 h62.5
  text "2 OZ." at 11910,6002.51 h62.5
  text "0.093" at 6895,5802.51 h62.5
  text "NONE" at 8095,5802.51 h62.5
  text "NONE" at 9395,5802.51 h62.5
  text "OTHER" at 10645,5802.51 h62.5
  text "OTHER" at 11910,5802.51 h62.5
  text "0.125" at 6895,5602.51 h62.5
  text "DESIGN" at 6873.07,5295.01 h75
  text "TRACE/GAP SPACING" at 8246.19,5289.65 h75
  text "LAYER COUNT" at 10813.65,5290.01 h75
  text "SMD" at 6845,5052.51 h62.5
  text "SINGLE SIDED" at 10360,5052.51 h62.5
  text "2 LAYER" at 11660,5052.51 h62.5
  text "0.010/0.010" at 8395,5048.04 h62.5
  text "THRU-HOLE" at 6845,4852.51 h62.5
  text "4 LAYER" at 10360,4852.51 h62.5
  text "6 LAYER" at 11660,4852.51 h62.5
  text "0.008/0.007" at 8395,4848.04 h62.5
  text "MIX" at 6845,4652.51 h62.5
  text "8 LAYER" at 10360,4652.51 h62.5
  text "10 LAYER" at 11660,4652.51 h62.5
  text "0.005/0.006" at 8395,4648.04 h62.5
  text "OTHER" at 10360,4452.51 h62.5
  text "NOTES: UNLESS OTHERWISE SPECIFIED" at 6645,4070.01 h100
  text "1." at 6645,3792.51 h62.5
  text "MATERIAL:" at 6820,3792.51 h62.5
  text "ALL MATERIALS,  INCLUDING BUT NOT LIMITED TO BASE LAMINATE,  BONDING MATERIALS" at 8195,3786.56 h62.5
  text "AND SOLDERMASK COATINGS FORMING THE FINISHED PRINTED CIRCUIT BOARD SHALL MEET" at 8195,3617.51 h62.5
  text "UL-796 REQUIREMENTS AND BE RoHS COMPLIANT AND HAVE A FLAMMABILITY OF UL94V-0." at 8195,3444.53 h62.5
  text "2." at 6645,3272.51 h62.5
  text "BASE LAMINATE:" at 6820,3272.51 h62.5
  text "PLASTIC SHEET, LAMINATED METAL CLAD, ONE OR TWO SIDES, BASE MATERIAL NEMA TYPE FR-4 OR" at 8195,3249.06 h62.5
  text "EQUIVALENT, W/Tg =140 Deg C OR HIGHER. MINIMUM DECOMPOSITION TEMP (Td) OF 320 Deg c." at 8195,3113.64 h62.5
  text "GLASS EPOXY RESIN, COPPER-CLAD IN ACCORDANCE WITH 4 LAYER STACK-UP," at 8145,2934.06 h62.5
  text "COMPLIANT WITH LEAD FREE PROCESS." at 8145,2815.01 h62.5
  text "3." at 6645,2592.51 h62.5
  text "SOLDERMASK:" at 6820,2592.51 h62.5
  text "SOLDERMASK OVER BARE COPPER (SMOBC) USING LIQUID PHOTO-IMAGEABLE SOLDERMASK IN" at 8195,2576.14 h62.5
  text "ACCORDANCE WITH IPC-SM-840. COLOR: GREEN. MINOR SOLDERMASK ADJUSTMENTS TO FACILITATE" at 8190,2437.51 h62.5
  text "PCB FAB AND OR ASSEMBLY IS ALLOWED PROVIDED NO DEFECTS ARE CREATED TO FINAL ASSEMBLY" at 8190,2312.51 h62.5
  text "AS A RESULT." at 8190,2187.51 h62.5
  text "4." at 6640,2007.51 h62.5
  text "TOLERANCES:" at 6815,2007.51 h62.5
  text "UNLESS OTHERWISE SPECIFIED PCB TOLERANCES" at 8195,1985.01 h62.5
  text "SHALL BE +/- .005 INCHES, HOLE DIAMETERS SHALL BE +/- .003 INCHES." at 8195,1854.06 h62.5
  text "5." at 6645,1667.51 h62.5
  text "PLATING:" at 6820,1667.51 h62.5
  text "HOLES REQUIRING PLATING, SEE HOLE CHART, TO HAVE 1 OZ. (0.0014) MIN. THK MIN." at 8195,1651.14 h62.5
  text "THICK COPPER." at 8195,1492.51 h62.5
  text "PLATE WITH RoHS COMPLIANT, IMMERSION SILVER PREFERRED, IMMERSION TIN OR Sn/Ag/Cu," at 8195,1294.59 h62.5
  text "6." at 6645,1292.51 h62.5
  text "FINISH:" at 6820,1292.51 h62.5
  text "WITH RMA FLUX, 0.0003\" to .0005\" THICK ALL EXPOSED AREAS" at 8195,1174.06 h62.5
  text "AS COATED, NO ACTIVE FLUXES ARE ACCEPTABLE." at 8195,991.56 h62.5
  text "7." at 6645,767.51 h62.5
  text "LEGEND:" at 6820,767.51 h62.5
  text "IF REQUIRED, SILKSCREEN LEGEND(S) WITH WHITE NON-CONDUCTIVE EPOXY INK." at 8195,751.14 h62.5
  text "8." at 6645,517.51 h62.5
  text "MARKINGS:" at 6820,517.51 h62.5
  text "BOARD MUST BEAR VENDOR'S IDENTIFICATION CODE (ETCH OR WHITE NON-CONDUCTIVE INK)." at 8195,501.14 h62.5
  text "LOCATION OPTIONAL." at 8195,367.51 h62.5
  text "9." at 6645,147.51 h62.5
  text "WORKMANSHIP:" at 6820,142.51 h62.5
  text "BOARD IS TO BE MANUFACTURED PER IPC-A-600 CLASS 2 REQUIREMENTS OR BETTER." at 8195,139.53 h62.5
  text "PCB VENDOR IS REQUIRED TO RETURN ANY AND ALL DOCUMENTS SUPPLIED OR ULTIMATELY PURCHASED BY TEXAS" at 8195,-85.47 h62.5
  text "DOCUMENTATION:" at 6820,-102.49 h62.5
  text "10." at 6570,-107.49 h62.5
  text "INSTRUMENTS UPON COMPLETION OF PURCHASE ORDER." at 8195,-282.49 h62.5
  text "11." at 6570,-507.49 h62.5
  text "DRILL SIZES:" at 6820,-507.49 h62.5
  text "HOLE DIAMETERS SHOWN ARE FINISHED SIZES AFTER PLATING UNLESS OTHERWISE NOTED." at 8195,-507.49 h62.5
  text "12." at 6570,-732.49 h62.5
  text "PANEL BORDER:" at 6820,-732.49 h62.5
  text "ANY METAL IN BORDER AREA INCLUDING PART NUMBER, DATECODE AND/OR REVISION LETTERS" at 8195,-738.44 h62.5
  text "MUST BE COVERED WITH SOLDERMASK." at 8195,-907.49 h62.5
  text "FB" at 5130.26,-1012.24 h62.5
  text "NO DIMENSIONAL, MATERIAL, OR PROCESS CHANGES ARE ALLOWED WITHOUT PRIOR EXPLICIT WRITTEN PERMISSION" at 8195,-1093.44 h62.5
  text "PROCESS CHANGES:" at 6820,-1107.49 h62.5
  text "13." at 6570,-1112.49 h62.5
  text "FROM TEXAS INSTRUMENTS." at 8195,-1287.49 h62.5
